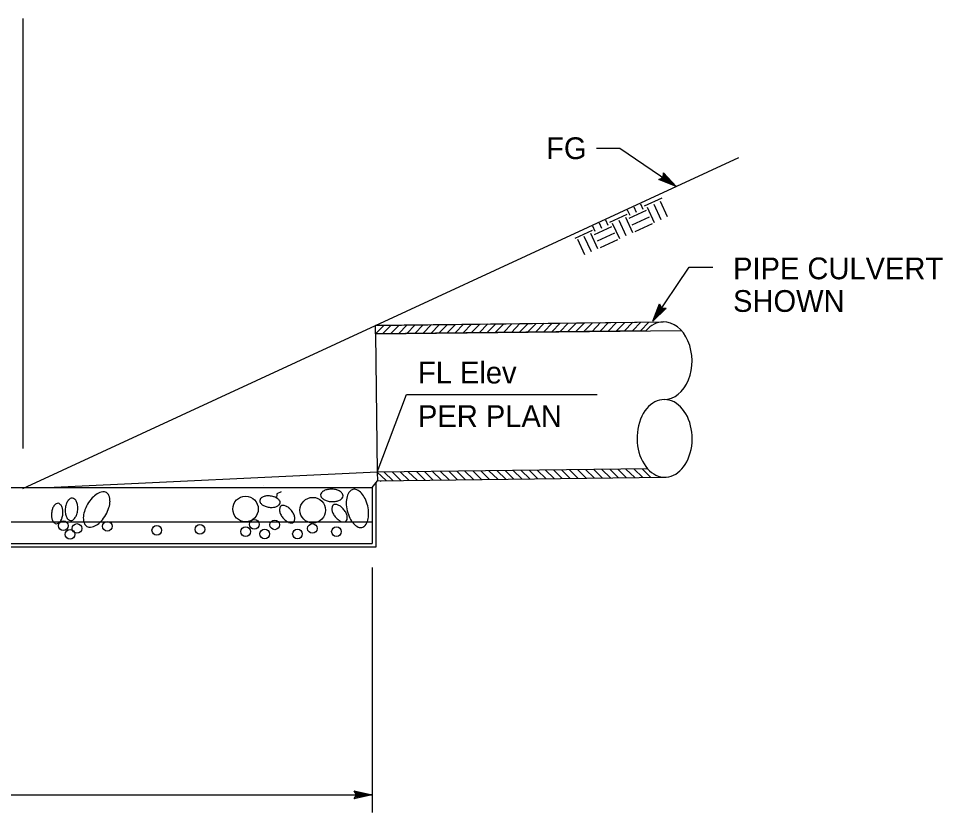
# Model space of a CAD drawing. Extents: x 6707692 to 6708868, y 1870875 to 1871658.
# Drawn here: x 6708616.9 to 6708867.5, y 1871262.9 to 1871478.3 of the extents above; entities that cross this region are included whole.
import ezdxf

# ---------------------------------------------------------------- set-up
doc = ezdxf.new("R2010")
doc.units = 0
doc.layers.add('Level 60', color=7, linetype='Continuous')

msp = doc.modelspace()

# ---------------------------------------------------------------- linework, layer by layer
at = {"layer": 'Level 60'}
for p, q in [((6708618.09, 1871478.32), (6708618.09, 1871361.62)), ((6708773.68, 1871443.17), (6708780.04, 1871443.17)), ((6708780.04, 1871443.17), (6708795.26, 1871432.75)), ((6708713.73, 1871395.05), (6708812.32, 1871440.63)), ((6708790.58, 1871434.62), (6708791.74, 1871435.14)), ((6708790.58, 1871434.62), (6708791.74, 1871435.14)), ((6708790.58, 1871434.62), (6708790.58, 1871434.62)), ((6708790.58, 1871434.62), (6708790.58, 1871434.62)), ((6708790.59, 1871434.63), (6708791.75, 1871435.16)), ((6708795.26, 1871432.75), (6708790.59, 1871434.63)), ((6708790.59, 1871434.63), (6708790.59, 1871434.63)), ((6708794.32, 1871433.39), (6708790.91, 1871434.76)), ((6708793.39, 1871434.03), (6708791.19, 1871434.92)), ((6708792.46, 1871434.67), (6708791.52, 1871435.05)), ((6708791.75, 1871435.16), (6708791.82, 1871436.43)), ((6708791.76, 1871435.43), (6708792.46, 1871434.67)), ((6708791.8, 1871435.74), (6708793.39, 1871434.03)), ((6708791.81, 1871436.09), (6708794.33, 1871433.39)), ((6708791.82, 1871436.43), (6708791.82, 1871436.43)), ((6708791.82, 1871436.43), (6708791.82, 1871436.43)), ((6708791.82, 1871436.43), (6708791.82, 1871436.43)), ((6708791.82, 1871436.43), (6708795.26, 1871432.75)), ((6708795.26, 1871432.75), (6708793.78, 1871433.77)), ((6708795.26, 1871432.75), (6708795.26, 1871432.75)), ((6708795.26, 1871432.75), (6708795.26, 1871432.75)), ((6708795.26, 1871432.75), (6708795.26, 1871432.75)), ((6708791.38, 1871429.53), (6708786.64, 1871427.35)), ((6708784.56, 1871425.69), (6708783.9, 1871427.11)), ((6708786.33, 1871426.5), (6708785.67, 1871427.93)), ((6708789.42, 1871422.89), (6708787.51, 1871427.05)), ((6708791.19, 1871423.71), (6708789.28, 1871427.86)), ((6708792.97, 1871424.52), (6708791.05, 1871428.68)), ((6708781.93, 1871425.17), (6708777.21, 1871423)), ((6708782.77, 1871424.86), (6708782.12, 1871426.29)), ((6708787.18, 1871426.18), (6708782.47, 1871424)), ((6708775.11, 1871421.33), (6708774.45, 1871422.75)), ((6708776.88, 1871422.14), (6708776.22, 1871423.57)), ((6708779.97, 1871418.53), (6708778.05, 1871422.69)), ((6708781.74, 1871419.35), (6708779.82, 1871423.5)), ((6708783.51, 1871420.16), (6708781.6, 1871424.32)), ((6708788, 1871424.4), (6708783.28, 1871422.23)), ((6708788.82, 1871422.63), (6708784.1, 1871420.46)), ((6708772.47, 1871420.81), (6708767.78, 1871418.64)), ((6708774.06, 1871415.8), (6708772.14, 1871419.96)), ((6708773.34, 1871420.51), (6708772.68, 1871421.93)), ((6708777.75, 1871421.82), (6708773.02, 1871419.64)), ((6708778.57, 1871420.05), (6708773.83, 1871417.87)), ((6708770.52, 1871414.17), (6708768.6, 1871418.32)), ((6708772.31, 1871414.99), (6708770.37, 1871419.14)), ((6708779.39, 1871418.28), (6708774.65, 1871416.1)), ((6708788.93, 1871396.23), (6708798.84, 1871410.81)), ((6708798.84, 1871410.81), (6708805.22, 1871410.81)), ((6708788.93, 1871396.23), (6708790.79, 1871400.91)), ((6708792.6, 1871399.68), (6708788.93, 1871396.23)), ((6708792.26, 1871399.69), (6708789.56, 1871397.16)), ((6708789.57, 1871397.17), (6708790.93, 1871400.58)), ((6708790.2, 1871398.1), (6708791.08, 1871400.3)), ((6708791.91, 1871399.7), (6708790.2, 1871398.1)), ((6708790.79, 1871400.91), (6708790.79, 1871400.91)), ((6708790.79, 1871400.91), (6708791.32, 1871399.75)), ((6708790.8, 1871400.89), (6708790.8, 1871400.89)), ((6708790.8, 1871400.89), (6708791.32, 1871399.74)), ((6708790.8, 1871400.89), (6708790.8, 1871400.89)), ((6708790.8, 1871400.89), (6708791.32, 1871399.74)), ((6708790.84, 1871399.03), (6708791.21, 1871399.98)), ((6708791.59, 1871399.74), (6708790.84, 1871399.03)), ((6708791.32, 1871399.75), (6708792.6, 1871399.68)), ((6708791.32, 1871399.74), (6708792.61, 1871399.67)), ((6708791.32, 1871399.74), (6708792.61, 1871399.67)), ((6708792.6, 1871399.68), (6708792.6, 1871399.68)), ((6708792.61, 1871399.67), (6708792.61, 1871399.67)), ((6708792.61, 1871399.67), (6708792.61, 1871399.67)), ((6708788.93, 1871396.23), (6708789.94, 1871397.71)), ((6708618.09, 1871350.82), (6708713.73, 1871395.05)), ((6708713.73, 1871395.06), (6708791.77, 1871395.99)), ((6708713.73, 1871395.05), (6708791.78, 1871395.99)), ((6708713.75, 1871392.72), (6708713.73, 1871395.05)), ((6708713.75, 1871392.72), (6708716.07, 1871395.08)), ((6708715.64, 1871392.74), (6708717.94, 1871395.11)), ((6708717.82, 1871392.75), (6708720.13, 1871395.13)), ((6708720, 1871392.79), (6708722.32, 1871395.16)), ((6708722.19, 1871392.81), (6708724.5, 1871395.18)), ((6708724.38, 1871392.84), (6708726.69, 1871395.21)), ((6708726.55, 1871392.86), (6708728.88, 1871395.24)), ((6708728.75, 1871392.88), (6708731.06, 1871395.25)), ((6708730.94, 1871392.92), (6708733.25, 1871395.29)), ((6708733.12, 1871392.94), (6708735.43, 1871395.31)), ((6708735.31, 1871392.98), (6708737.61, 1871395.34)), ((6708737.5, 1871392.99), (6708739.81, 1871395.37)), ((6708739.67, 1871393.02), (6708742, 1871395.4)), ((6708741.86, 1871393.05), (6708744.18, 1871395.42)), ((6708744.05, 1871393.07), (6708746.37, 1871395.45)), ((6708746.23, 1871393.1), (6708748.55, 1871395.48)), ((6708748.42, 1871393.12), (6708750.73, 1871395.5)), ((6708750.62, 1871393.15), (6708752.92, 1871395.52)), ((6708752.79, 1871393.18), (6708755.11, 1871395.55)), ((6708754.98, 1871393.21), (6708757.29, 1871395.57)), ((6708757.17, 1871393.23), (6708759.48, 1871395.61)), ((6708759.35, 1871393.26), (6708761.67, 1871395.64)), ((6708761.53, 1871393.28), (6708763.84, 1871395.65)), ((6708763.72, 1871393.3), (6708766.03, 1871395.69)), ((6708765.9, 1871393.34), (6708768.22, 1871395.7)), ((6708768.1, 1871393.36), (6708770.41, 1871395.74)), ((6708770.28, 1871393.38), (6708772.6, 1871395.75)), ((6708772.46, 1871393.41), (6708774.78, 1871395.79)), ((6708774.66, 1871393.45), (6708776.96, 1871395.81)), ((6708776.84, 1871393.47), (6708779.14, 1871395.83)), ((6708779.02, 1871393.5), (6708781.34, 1871395.87)), ((6708781.22, 1871393.52), (6708783.53, 1871395.89)), ((6708783.4, 1871393.54), (6708785.71, 1871395.93)), ((6708785.58, 1871393.57), (6708787.9, 1871395.94)), ((6708788.93, 1871396.23), (6708788.93, 1871396.23)), ((6708788.93, 1871396.23), (6708788.93, 1871396.23)), ((6708788.93, 1871396.23), (6708788.93, 1871396.23)), ((6708713.75, 1871392.72), (6708796.64, 1871393.7)), ((6708787.11, 1871393.58), (6708713.75, 1871392.72)), ((6708713.75, 1871392.72), (6708714.21, 1871355.24)), ((6708714.21, 1871355.24), (6708626.6, 1871351.02)), ((6708787.56, 1871356.12), (6708714.21, 1871355.24)), ((6708714.21, 1871355.24), (6708714.23, 1871352.89)), ((6708714.21, 1871355.24), (6708716.58, 1871352.92)), ((6708716.09, 1871355.26), (6708718.45, 1871352.95)), ((6708718.26, 1871355.27), (6708720.63, 1871352.97)), ((6708720.46, 1871355.31), (6708722.83, 1871352.99)), ((6708722.63, 1871355.34), (6708725.02, 1871353.02)), ((6708724.82, 1871355.36), (6708727.21, 1871353.05)), ((6708727.02, 1871355.39), (6708729.38, 1871353.07)), ((6708729.21, 1871355.42), (6708731.57, 1871353.1)), ((6708731.38, 1871355.44), (6708733.75, 1871353.13)), ((6708733.58, 1871355.46), (6708735.93, 1871353.15)), ((6708735.75, 1871355.49), (6708738.12, 1871353.18)), ((6708737.94, 1871355.51), (6708740.31, 1871353.21)), ((6708740.13, 1871355.54), (6708742.5, 1871353.22)), ((6708742.32, 1871355.58), (6708744.69, 1871353.26)), ((6708744.51, 1871355.6), (6708746.87, 1871353.29)), ((6708746.69, 1871355.62), (6708749.05, 1871353.31)), ((6708748.87, 1871355.65), (6708751.25, 1871353.35)), ((6708751.06, 1871355.67), (6708753.43, 1871353.37)), ((6708753.25, 1871355.7), (6708755.61, 1871353.4)), ((6708755.43, 1871355.73), (6708757.8, 1871353.42)), ((6708757.62, 1871355.76), (6708759.98, 1871353.45)), ((6708759.8, 1871355.79), (6708762.16, 1871353.48)), ((6708761.98, 1871355.81), (6708764.37, 1871353.49)), ((6708764.17, 1871355.84), (6708766.54, 1871353.53)), ((6708766.36, 1871355.87), (6708768.73, 1871353.54)), ((6708768.55, 1871355.9), (6708770.92, 1871353.58)), ((6708770.74, 1871355.92), (6708773.1, 1871353.61)), ((6708772.92, 1871355.94), (6708775.28, 1871353.63)), ((6708775.1, 1871355.97), (6708777.48, 1871353.66)), ((6708777.29, 1871356), (6708779.65, 1871353.68)), ((6708779.48, 1871356.03), (6708781.85, 1871353.71)), ((6708781.65, 1871356.05), (6708784.04, 1871353.73)), ((6708783.84, 1871356.08), (6708786.22, 1871353.76)), ((6708786.03, 1871356.1), (6708788.39, 1871353.78)), ((6708714.24, 1871352.89), (6708792.3, 1871353.84)), ((6708461.68, 1871351.02), (6708712.86, 1871351.02)), ((6708683.45, 1871351.72), (6708683.45, 1871351.72)), ((6708683.45, 1871351.72), (6708683.45, 1871351.72)), ((6708686.98, 1871349.33), (6708686.89, 1871348.04)), ((6708686.98, 1871349.33), (6708686.89, 1871348.04)), ((6708688.13, 1871349.86), (6708686.98, 1871349.33)), ((6708688.13, 1871349.86), (6708686.98, 1871349.33)), ((6708688.13, 1871349.86), (6708688.13, 1871349.86)), ((6708688.13, 1871349.86), (6708688.13, 1871349.86)), ((6708686.89, 1871348.04), (6708686.89, 1871348.04)), ((6708686.89, 1871348.04), (6708686.89, 1871348.04)), ((6708461.68, 1871341.75), (6708712.86, 1871341.75)), ((6708713.84, 1871334.86), (6708460.69, 1871334.86)), ((6708461.68, 1871335.85), (6708712.86, 1871335.85)), ((6708712.86, 1871329.39), (6708712.86, 1871262.87)), ((6708461.68, 1871267.7), (6708712.86, 1871267.7)), ((6708708.6, 1871267.7), (6708707.94, 1871268.8)), ((6708707.94, 1871268.8), (6708707.94, 1871268.8)), ((6708707.94, 1871268.8), (6708712.86, 1871267.7)), ((6708712.86, 1871267.7), (6708707.94, 1871266.61)), ((6708707.94, 1871266.61), (6708708.6, 1871267.7)), ((6708707.94, 1871266.61), (6708707.94, 1871266.61)), ((6708708.12, 1871268.51), (6708711.73, 1871267.7)), ((6708711.72, 1871267.7), (6708708.13, 1871266.91)), ((6708710.59, 1871267.7), (6708708.28, 1871267.19)), ((6708708.31, 1871268.21), (6708710.59, 1871267.7)), ((6708708.45, 1871267.93), (6708709.46, 1871267.7)), ((6708709.46, 1871267.7), (6708708.47, 1871267.48)), ((6708712.86, 1871267.7), (6708711.06, 1871267.7)), ((6708712.86, 1871267.7), (6708712.86, 1871267.7))]:
    msp.add_line(p, q, dxfattribs=at)
for points in [[(6708714.21, 1871355.24), (6708722.1, 1871376.33), (6708773.89, 1871376.33)], [(6708712.86, 1871351.02), (6708714.24, 1871352.89)], [(6708713.84, 1871352.34), (6708713.84, 1871334.86)], [(6708715.02, 1871352.9), (6708715.13, 1871352.72), (6708715.2, 1871352.9)], [(6708712.86, 1871351.02), (6708712.86, 1871335.85)]]:
    msp.add_lwpolyline(points, dxfattribs=at)
for centre, radius in [((6708678.47, 1871345.22), 3.47), ((6708696.71, 1871344.91), 3.47), ((6708629.04, 1871340.68), 1.31), ((6708640.98, 1871340.55), 1.31), ((6708680.86, 1871341.05), 1.31), ((6708686.4, 1871340.92), 1.31), ((6708630.88, 1871338.34), 1.31), ((6708632.73, 1871339.94), 1.31), ((6708654.4, 1871339.45), 1.31), ((6708666.09, 1871339.69), 1.31), ((6708678.52, 1871339.08), 1.31), ((6708683.69, 1871338.46), 1.31), ((6708692.56, 1871338.46), 1.31), ((6708696.62, 1871339.94), 1.31), ((6708703.14, 1871339.08), 1.31)]:
    msp.add_circle(centre, radius, dxfattribs=at)
for centre, radius, start, end in [((6708641.51, 1871343.97), 6.29, 121.6811, 137.3954), ((6708640.22, 1871346.07), 3.82, 97.5555, 121.6811), ((6708639.93, 1871348.27), 1.61, 59.9552, 97.5555), ((6708639.93, 1871348.27), 1.61, 22.3549, 59.9552), ((6708699.81, 1871349), 0.975, 140.6402, 177.4953), ((6708700.77, 1871348.22), 2.21, 116.4195, 140.6402), ((6708701.38, 1871347), 3.57, 100.3875, 116.4195), ((6708701.73, 1871345.09), 5.51, 87.4953, 100.3875), ((6708701.73, 1871345.09), 5.51, 74.6031, 87.4953), ((6708702.24, 1871346.96), 3.57, 58.5711, 74.6031), ((6708702.95, 1871348.12), 2.21, 34.3504, 58.5711), ((6708703.97, 1871348.82), 0.975, 357.4953, 34.3504), ((6708709.7, 1871347.59), 3.82, 140.9226, 165.0482), ((6708707.98, 1871348.98), 1.61, 103.3223, 140.9226), ((6708707.98, 1871348.98), 1.61, 65.722, 103.3223), ((6708707.07, 1871346.97), 3.82, 41.5964, 65.722), ((6708705.23, 1871345.33), 6.29, 25.8821, 41.5964), ((6708633.22, 1871345.4), 3.57, 146.1522, 162.1843), ((6708632.09, 1871346.16), 2.21, 121.9316, 146.1522), ((6708631.44, 1871347.21), 0.975, 85.0765, 121.9316), ((6708631.44, 1871347.21), 0.975, 48.2213, 85.0765), ((6708630.61, 1871346.29), 2.21, 24.0007, 48.2213), ((6708629.37, 1871345.73), 3.57, 7.9686, 24.0007), ((6708644.11, 1871341.58), 9.82, 137.3954, 149.9552), ((6708637.88, 1871347.43), 3.82, 358.2293, 22.3549), ((6708635.42, 1871347.5), 6.29, 342.515, 358.2293), ((6708683.21, 1871347.46), 0.886, 172.7877, 209.6428), ((6708683.21, 1871347.46), 0.886, 135.9326, 172.7877), ((6708684.18, 1871348.02), 2.01, 209.6428, 233.8635), ((6708684.02, 1871346.68), 2.01, 111.7119, 135.9326), ((6708684.47, 1871345.53), 3.25, 95.6799, 111.7119), ((6708684.65, 1871343.77), 5.01, 82.7877, 95.6799), ((6708684.65, 1871343.77), 5.01, 69.8955, 82.7877), ((6708685.25, 1871345.43), 3.25, 53.8635, 69.8955), ((6708685.98, 1871346.43), 2.01, 29.6428, 53.8635), ((6708686.96, 1871346.98), 0.886, 315.9326, 352.7877), ((6708686.96, 1871346.98), 0.886, 352.7877, 29.6428), ((6708699.81, 1871349), 0.975, 177.4953, 214.3504), ((6708700.84, 1871349.7), 2.21, 214.3504, 238.5711), ((6708701.55, 1871350.86), 3.57, 238.5711, 254.6031), ((6708702.06, 1871352.74), 5.51, 254.6031, 267.4953), ((6708702.06, 1871352.74), 5.51, 267.4953, 280.3875), ((6708702.41, 1871350.83), 3.57, 280.3875, 296.4195), ((6708703.02, 1871349.61), 2.21, 296.4195, 320.6402), ((6708703.97, 1871348.82), 0.975, 320.6402, 357.4953), ((6708712.08, 1871346.95), 6.29, 165.0482, 180.7625), ((6708715.61, 1871347), 9.82, 180.7625, 193.3223), ((6708702.05, 1871343.79), 9.82, 13.3223, 25.8821), ((6708630.84, 1871343.7), 5.01, 162.1843, 175.0765), ((6708629.16, 1871344.24), 3.25, 146.1522, 162.1843), ((6708628.13, 1871344.93), 2.01, 121.9316, 146.1522), ((6708627.54, 1871345.89), 0.886, 85.0765, 121.9316), ((6708627.54, 1871345.89), 0.886, 48.2213, 85.0765), ((6708626.79, 1871345.05), 2.01, 24.0007, 48.2213), ((6708625.66, 1871344.54), 3.25, 7.9686, 24.0007), ((6708623.91, 1871344.3), 5.01, 355.0765, 7.9686), ((6708635.07, 1871344.81), 5.51, 175.0765, 187.9686), ((6708635.07, 1871344.81), 5.51, 162.1843, 175.0765), ((6708627.45, 1871345.46), 5.51, 342.1843, 355.0765), ((6708627.45, 1871345.46), 5.51, 355.0765, 7.9686), ((6708640.74, 1871342.65), 6.29, 162.515, 178.2293), ((6708644.11, 1871341.58), 9.82, 149.9552, 162.515), ((6708632.05, 1871348.56), 9.82, 329.9552, 342.515), ((6708684.91, 1871349.01), 3.25, 233.8635, 249.8955), ((6708685.52, 1871350.67), 5.01, 249.8955, 262.7877), ((6708685.52, 1871350.67), 5.01, 262.7877, 275.6799), ((6708685.69, 1871348.92), 3.25, 275.6799, 291.7119), ((6708686.15, 1871347.77), 2.01, 291.7119, 315.9326), ((6708689.68, 1871345.02), 2.01, 165.2987, 189.5193), ((6708690.9, 1871345.22), 3.25, 189.5193, 205.5514), ((6708688.59, 1871345.3), 0.886, 128.4436, 165.2987), ((6708688.59, 1871345.3), 0.886, 91.5884, 128.4436), ((6708688.62, 1871344.18), 2.01, 67.3678, 91.5884), ((6708688.15, 1871343.04), 3.25, 51.3357, 67.3678), ((6708687.04, 1871341.66), 5.01, 38.4436, 51.3357), ((6708687.04, 1871341.66), 5.01, 25.5514, 38.4436), ((6708703.88, 1871345.28), 2.01, 165.2987, 189.5193), ((6708705.1, 1871345.49), 3.25, 189.5193, 205.5514), ((6708702.79, 1871345.57), 0.886, 128.4436, 165.2987), ((6708702.79, 1871345.57), 0.886, 91.5884, 128.4436), ((6708702.83, 1871344.44), 2.01, 67.3678, 91.5884), ((6708702.35, 1871343.3), 3.25, 51.3357, 67.3678), ((6708701.25, 1871341.92), 5.01, 38.4436, 51.3357), ((6708701.25, 1871341.92), 5.01, 25.5514, 38.4436), ((6708715.61, 1871347), 9.82, 193.3223, 205.8821), ((6708702.05, 1871343.79), 9.82, 0.7625, 13.3223), ((6708630.84, 1871343.7), 5.01, 175.0765, 187.9686), ((6708629.09, 1871343.46), 3.25, 187.9686, 204.0007), ((6708627.96, 1871342.95), 2.01, 204.0007, 228.2213), ((6708626.62, 1871343.07), 2.01, 301.9316, 326.1522), ((6708625.59, 1871343.76), 3.25, 326.1522, 342.1843), ((6708623.91, 1871344.3), 5.01, 342.1843, 355.0765), ((6708633.15, 1871344.54), 3.57, 187.9686, 204.0007), ((6708631.9, 1871343.99), 2.21, 204.0007, 228.2213), ((6708631.08, 1871343.06), 0.975, 228.2213, 265.0765), ((6708631.08, 1871343.06), 0.975, 265.0765, 301.9316), ((6708630.42, 1871344.11), 2.21, 301.9316, 326.1522), ((6708629.29, 1871344.87), 3.57, 326.1522, 342.1843), ((6708638.28, 1871342.72), 3.82, 178.2293, 202.3549), ((6708634.65, 1871346.17), 6.29, 301.6811, 317.3954), ((6708632.05, 1871348.56), 9.82, 317.3954, 329.9552), ((6708692.49, 1871345.98), 5.01, 205.5514, 218.4436), ((6708692.49, 1871345.98), 5.01, 218.4436, 231.3357), ((6708691.39, 1871344.61), 3.25, 231.3357, 247.3678), ((6708690.94, 1871342.34), 0.886, 308.4436, 345.2987), ((6708688.63, 1871342.42), 3.25, 9.5193, 25.5514), ((6708689.85, 1871342.62), 2.01, 345.2987, 9.5193), ((6708706.69, 1871346.25), 5.01, 205.5514, 218.4436), ((6708706.69, 1871346.25), 5.01, 218.4436, 231.3357), ((6708705.59, 1871344.87), 3.25, 231.3357, 247.3678), ((6708705.12, 1871343.73), 2.01, 247.3678, 271.5884), ((6708705.15, 1871342.6), 0.886, 271.5884, 308.4436), ((6708705.15, 1871342.6), 0.886, 308.4436, 345.2987), ((6708702.84, 1871342.68), 3.25, 9.5193, 25.5514), ((6708704.06, 1871342.89), 2.01, 345.2987, 9.5193), ((6708712.44, 1871345.46), 6.29, 205.8821, 221.5964), ((6708707.96, 1871343.2), 3.82, 320.9226, 345.0482), ((6708705.58, 1871343.83), 6.29, 345.0482, 0.7625), ((6708627.21, 1871342.11), 0.886, 228.2213, 265.0765), ((6708627.21, 1871342.11), 0.886, 265.0765, 301.9316), ((6708636.23, 1871341.88), 1.61, 202.3549, 239.9552), ((6708636.23, 1871341.88), 1.61, 239.9552, 277.5555), ((6708635.94, 1871344.07), 3.82, 277.5555, 301.6811), ((6708690.91, 1871343.46), 2.01, 247.3678, 271.5884), ((6708690.94, 1871342.34), 0.886, 271.5884, 308.4436), ((6708710.59, 1871343.82), 3.82, 221.5964, 245.722), ((6708709.68, 1871341.8), 1.61, 245.722, 283.3223), ((6708709.68, 1871341.8), 1.61, 283.3223, 320.9226)]:
    msp.add_arc(centre, radius, start, end, dxfattribs=at)
for centre, major_axis, ratio, start_param, end_param in [((6708791.9, 1871385.45), (-0.13, 10.54), 0.709759, 0.000058, 0.679669), ((6708791.9, 1871385.46), (0.13, -10.54), 0.730091, 0, 3.141593), ((6708792.16, 1871364.38), (0.13, -10.54), 0.709759, 6.23222, 11.886701), ((6708792.16, 1871364.38), (0.13, -10.54), 0.709759, 5.603516, 6.283127)]:
    msp.add_ellipse(centre, major_axis=major_axis, ratio=ratio, start_param=start_param, end_param=end_param, dxfattribs=at)

# ---------------------------------------------------------------- texts
for s, height, p in [('FG', 5.902, (6708760.02, 1871440.16)), ('PIPE CULVERT', 5.9, (6708810.73, 1871407.56)), ('SHOWN', 5.9, (6708810.73, 1871398.71)), ('FL Elev', 5.9, (6708725.25, 1871379.28)), ('PER PLAN', 5.9, (6708725.25, 1871367.48))]:
    msp.add_text(s, height=height, dxfattribs=at).set_placement(p)

doc.saveas('drawing.dxf')
